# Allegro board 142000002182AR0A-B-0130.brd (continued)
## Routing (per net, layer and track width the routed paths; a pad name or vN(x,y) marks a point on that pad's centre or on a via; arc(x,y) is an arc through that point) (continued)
GND_1: length 19.4
  TOP w0.508: H1.5 21.23,24.93 C4.1 24.06,25.17 H1.4 ; 21.23,34.73 C3.1 ; 21.23,34.73 22.42,34.73 23.08,34.07 H1.2 ; 21.23,34.73 H1.1
GND_2: length 19.4
  TOP w0.508: H2.1 78.23,41.64 C23.1 76.37,44.16 H2.8 76.02,40.51 C22.1 73.34,39 H2.7
GND_3: length 20.5
  TOP w0.508: H4.4 206.08,34.07 C63.1 202.37,34.31 H4.6 198.77,37.14 C61.1 200.82,38.23 H4.7
GND_5: length 21.8
  TOP w0.508: H5.8 199.59,6.86 C62.1 199.5,3.14 H5.6 ; H5.2 208.84,6.86 C66.1 208.93,3.14 H5.4
GND_6: length 16.3
  TOP w0.381: 81.01,3.3 84.25,3.3 C24.1 83.32,5 H3.3 ; 75.44,3.68 C21.1 73.02,5 H3.7
GND_7: length 24.3
  TOP w0.508: H7.2 349.3,6.86 C114.1 349.4,3.14 H7.4 ; H7.6 338.69,3.14 C112.1 338.78,6.86 H7.8
GND_8: length 22.9
  TOP w0.508: H6.4 349.61,37.14 C115.1 349.59,40.86 H6.2 ; H6.7 341.7,38.86 341.67,38.89 337.41,38.89 C113.1 337.39,38.03 338.45,36.96 342.42,36.96 H6.6
GND_9: length 23.9
  TOP w0.508: H8.4 405.92,26.14 C141.1 406.82,29.86 H8.2 403.32,33.23 C138.1 399.61,33.77 H8.8
VCC_12P_FAN1_IN: length 3.8
  TOP w0.381: C9.2 31.44,40.97 31.5,41.02 ; C9.2 v3(32.31,40.26) ; C9.2 31.44,39.55 31.5,39.5
  TOP w0.508: 29.72,34.54 C6.1 29.03,33.84
  vias: v1(31.24,40.26) v3(31.04,42.16) v3(32.31,42.16) v3(32.31,41.27) v3(32.31,38.99)
VCC_12P_FAN1_OUT: length 4.7
  TOP w0.381: 39.12,33.53 39.06,33.58 C14.1 40.26,34.54
  TOP w0.508: C12.1 35.99,39.7 35.94,39.75 ; C12.1 36.7,40.64 ; C12.1 37.41,39.7 37.47,39.75
  vias: v1(36.32,41.66) v3(35.69,43.94) v3(36.83,43.94) v3(36.83,42.93) v3(38.03,43.94) v3(38.03,42.93)
VCC_12P_FAN2_IN: length 5.9
  TOP w0.508: C31.2 100.08,38.81 100.08,38.1 ; C31.2 99.9,40.19 99.82,40.26 ; C31.2 100.84,38.99 v3(101.22,39.37) ; 94.11,36.58 94.16,36.63 C28.1 95.25,35.69
  vias: v1(100.05,40.72) v3(99.94,42.16) v3(101.21,42.16) v3(101.21,41.27) v3(101.21,40.26)
VCC_12P_FAN2_OUT: length 3.3
  TOP w0.508: 106.55,35.43 106.37,35.61 C34.1 107.19,36.45 ; 105.1,42.36 C33.1 105.66,41.53
  vias: v1(104.9,42.29) v3(103.5,44.83) v3(104.13,43.56) v3(104.64,44.83) v3(105.79,44.07) v3(105.79,43.05)
VCC_12P_FAN3_IN: length 5.5
  TOP w0.508: C48.1 169.24,38.55 C50.2 ; 169.24,40.31 C50.2 ; C50.2 169.93,39.62 ; 167.77,33.4 167.71,33.45 C47.1 168.91,34.54
  vias: v1(169.42,40.01) v3(168.91,42.16) v3(168.91,41.27) v3(170.05,42.93) v3(170.05,41.78) v3(170.05,40.77)
VCC_12P_FAN3_OUT: length 4.8
  TOP w0.381: 174.17,39.7 C53.1 ; C53.1 174.88,40.39 ; C53.1 175.46,39.7
  TOP w0.508: 178.69,34.54 C55.1 177.24,33.58 177.55,33.27
  vias: v1(175.9,42.04) v3(173.16,43.43) v3(173.74,42.55) v3(174.3,43.43) v3(174.88,42.55) v3(175.51,43.43)
VCC_12P_FAN4_IN: length 4.1
  TOP w0.508: C87.2 237.44,39.7 ; C87.2 238.12,38.99 ; C87.2 237.44,38.41 237.49,38.35 ; 231.27,36.32 231.34,36.25 C84.1 232.28,35.43 232.41,35.31
  vias: v1(237.87,40.77) v3(237.74,42.16) v3(239.01,42.16) v3(239.01,41.27) v3(239.01,40.26) v3(239.01,38.99)
VCC_12P_FAN4_OUT: length 3.8
  TOP w0.508: 242.95,43.05 243.02,42.98 C89.1 243.71,42.42 ; C90.1 243.84,37.34 ; C90.1 243.02,37.54 243.46,37.97 ; C90.1 243.02,36.48
  vias: v1(242.82,42.16) v3(241.3,44.83) v3(241.94,43.56) v3(242.44,44.83) v3(244.6,43.43) v3(244.6,42.42)
VCC_12P_FAN5_IN: length 5
  TOP w0.381: C99.1 303.53,37.67 C98.2 304.04,38.23 304.17,38.35 ; 303.91,32.89 303.78,32.77 C97.1 302.84,32.06 302.89,32
  vias: v1(307.98,41.27) v3(305.82,38.86) v3(306.32,39.62) v3(306.7,38.86) v3(307.21,39.62) v3(307.72,38.86) v3(308.23,39.62)
VCC_12P_FAN5_OUT: length 5.1
  TOP w0.381: 312.8,35.81 312.8,36.9 C105.1 313.44,37.47 ; 313.06,32.38 312.93,32.26 C104.1 312.11,31.3 312.17,31.24
  vias: v1(311.79,44.2) v3(310.77,42.8) v3(310.77,41.91) v3(311.91,42.8) v3(311.91,41.91) v3(313.18,42.8) v3(313.18,41.78)
VCC_12P_FAN6_IN: length 5.4
  TOP w0.381: 372.75,38.99 C119.2 372.24,38.3 C120.1
  TOP w0.508: 372.36,33.91 C118.1 371.17,33.33 371.6,32.89
  vias: v1(376.3,44.83) v3(374.06,38.9) v3(374.2,39.83) v3(374.79,39.26) v3(374.87,40.29) v3(375.6,39.32) v3(375.67,40.13)
VCC_12P_FAN6_OUT: length 6
  TOP w0.381: 380.49,42.16 380.69,41.96 C126.1 381.76,41.27 ; 382.27,35.18 382.09,35.36 C130.1 ; C129.1 382.09,37.65 C130.1 ; C130.1 383.41,36.2
  vias: v1(379.48,45.34) v3(380.87,43.05) v3(381.38,42.29) v3(381.76,43.05) v3(382.19,42.29) v3(382.65,43.05) v3(383,42.16)
VCC_CL_FAN1F: length 1
  BOTTOM w0.381: v3(39.24,28.83) v1(38.23,28.83)
VCC_CL_FAN1R: length 1.5
  BOTTOM w0.381: v1(31.42,27.41) 30.38,28.45 v3(30.35,28.45)
VCC_CL_FAN2F: length 0.9
  BOTTOM w0.381: v3(106.43,31.5) v1(105.51,31.5)
VCC_CL_FAN2R: length 0.9
  BOTTOM w0.381: v3(88.9,36.83) v1(88.9,35.92)
VCC_CL_FAN3F: length 1.2
  BOTTOM w0.381: v3(177.42,28.19) v1(176.59,29.02)
VCC_CL_FAN3R: length 1.1
  BOTTOM w0.381: v3(167.77,28.45) v1(167.77,29.59)
VCC_CL_FAN4F: length 1
  BOTTOM w0.381: v3(243.46,32.26) v1(243.46,31.24)
VCC_CL_FAN4R: length 1
  BOTTOM w0.381: v3(226.19,35.69) v1(226.19,36.7)
VCC_CL_FAN5F: length 1.3
  BOTTOM w0.254: v1(310.9,25.53) 312.04,25.53 v3(312.17,25.65)
VCC_CL_FAN5R: length 1.1
  BOTTOM w0.254: v1(302.77,26.29) v3(303.91,26.29)
VCC_CL_FAN6F: length 1.2
  BOTTOM w0.254: v3(381.89,29.97) 381.51,30.35 v1(381.51,30.99)
VCC_CL_FAN6R: length 1
  BOTTOM w0.254: v1(371.35,28.83) v3(372.36,28.83)
VCCA_FAN_CPLD: length 64.2
  TOP w0.254: U7.D3 v2(133.48,21.34) ; U7.D4 v2(133.48,20.54) ; U7.D10 133.47,15.75 v2(133.48,15.75) ; U7.K4 v2(127.88,21.34) ; U7.K9 v2(128.68,17.34)
  TOP w0.381: v3(137.42,7.24) 137.03,6.86 L9.2 137.03,5.21 v3(136.53,4.7) ; v3(144.29,12.73) 144.71,13.14 145.74,13.14 146.94,14.35 146.94,21.95 v3(147.32,22.33)
  BOTTOM w0.33: 132.47,16.77 133.48,15.76 v2(133.48,15.75)
  BOTTOM w0.381: v2(133.48,15.75) 133.48,15.61 133.93,15.16 C159.1 133.93,13.05 134.87,12.11 134.87,6.61 136.53,4.95 v3(136.53,4.7) ; 132.47,16.77 130.05,16.77 129.54,17.28 C151.1 128.7,17.33 v2(128.68,17.34) 128.68,18.95 127.82,19.82 C147.1 127.82,21.27 v2(127.88,21.34) ; v2(133.48,20.54) v2(133.48,21.34) 133.6,21.46 134.82,21.46 C161.1 135.41,21.23 137.77,21.23 137.93,21.07 138.65,21.07 139.46,21.88 139.95,21.88 140.48,22.42 146.37,22.42 146.46,22.33 v3(147.32,22.33) ; v3(137.42,7.24) 137.42,7.27 140.31,10.16 v1(140.31,10.31) 141.13,11.13 141.61,11.13 142.54,12.06 143.38,12.06 144.04,12.73 v3(144.29,12.73)
VDD3P3: length 1337.3
  TOP w0.254: v2(131.08,19.74) U7.G6 v2(130.28,18.94) U7.H7 U7.G8 ; v2(128.68,21.34) 129.08,21.74 U7.J3 v2(128.68,22.14) U7.K3 ; U7.G8 U7.F7 v2(131.88,18.94) ; U7.G8 v2(131.08,17.34) ; U7.J11 v2(129.48,14.94) ; U7.G11 v2(131.08,15.74) U7.F11 ; U7.F11 v2(131.88,14.94) ; U7.F11 v2(131.88,15.74) ; v2(131.88,22.94) U7.F2 v2(131.08,22.14) U7.G3 ; v2(127.88,17.34) 127.88,17.47 127.61,17.74 U7.L8 v2(127.88,18.14) U7.L7 v2(127.88,18.94) U7.L6 ; U7.H11 v2(129.48,15.74)
  TOP w0.381: C45.2 163.4,22.66 165.24,20.81 CONN3.4 ; LED6.A1 419.14,47 420.45,48.31 C142.1 420.41,48.4 LED6.A2 ; 355.6,35.1 355.6,22.61 v3(354.71,21.72) ; 355.6,35.1 360.72,40.22 372.77,40.22 373.89,41.34 R150.1 ; 355.6,35.1 353.28,37.42 353.28,40.18 352.43,41.03 C116.1 ; R16.2 44.5,5.92 v3(44.58,5.84) ; R62.2 126.49,27.84 v3(126.85,27.48) ; R19.2 v3(58.42,5.84) R23.2 ; v3(93.34,27.69) 94.49,28.83 R31.1 ; 145.16,4.95 145.09,5.03 R88.2 144.76,6.17 v3(144.28,6.17) 143.79,6.17 R80.2 143.46,5.51 144.02,4.95 ; R73.2 R74.2 R75.2 R76.2 v3(144.27,21.56) R82.2 ; R3.2 v3(13.72,12.45) ; v3(170.69,22.23) 174.22,25.76 174.22,32.99 R106.1 ; C116.1 352.29,47.82 352.02,47.82 351.43,48.4 LED5.A2 ; C116.1 352.15,47.68 351.47,47 LED5.A1 ; v3(115.06,25.02) 115.86,25.02 117.76,23.11 R54.2 R55.2 ; U7.C7 v2(133.48,18.94) U7.C6 ; LED4.A2 LED4.A1 280.34,46.7 C96.1 276.35,45.59 260.73,29.97 v3(260.73,21.84) ; R129.1 249.68,36.58 250.19,36.07 250.19,33.78 250.5,33.47 Q10.5 252.15,32.62 C95.1 252.15,30.83 250.85,29.53 247.42,29.53 245.45,27.56 233.68,27.56 231.52,29.72 R124.1 ; 11.18,40.25 28.93,40.25 29.27,40.59 29.27,42.78 R7.1 ; R4.2 13.74,11.05 v3(13.72,11.07) ; R5.2 R6.2 v3(16.76,18.67) ; R2.2 v3(14.1,13.84) ; U8.16 153.25,19.27 152.58,18.59 C44.1 C43.1 v3(150.11,18.59) ; R138.1 309.32,30.79 310.39,29.72 v3(310.39,19.3) ; R1.2 v3(14.1,15.11) ; v3(299.72,21.21) 298.96,21.97 298.96,39.05 299.34,39.43 305.12,39.43 305.56,39.88 R136.1 ; U7.C8 v2(134.28,17.34)
  TOP w0.508: v3(149.96,9.64) R90.2 149.13,10.44 149.1,10.41 ; v3(113.92,13.72) R40.1 R41.1 ; LED2.A1 LED2.A2 144.11,48.6 C42.1 144.83,46.05 150.66,40.22 162.05,40.22 ; R83.2 R84.2 R85.2 R86.2 R87.2 v3(146,14.43) ; v3(137.12,8) 136.27,8 135.51,7.24 L9.1 135.51,4.97 v3(135.19,4.65) ; 213.67,39.88 213.79,40.01 235.44,40.01 235.9,40.47 235.9,42.27 237.11,43.48 R125.1 ; 213.67,39.88 213.67,36.53 203.27,26.14 193.14,26.14 v3(188.47,21.46) ; 213.67,39.88 C69.1 212.95,48.6 LED3.A2 LED3.A1 ; Q1.5 17.62,32.23 18.16,32.77 C2.1 17.6,34.22 17.37,34.44 17.37,35.59 v3(17.27,35.69) 16.89,36.07 C1.1 15.95,36.88 15.3,37.53 Q2.5 ; R92.2 151.89,14.23 151.13,13.47 v3(149.87,13.47) 149.87,18.35 v3(150.11,18.59) ; C71.1 214.2,17.1 ; C71.1 C72.1 ; C71.1 214.78,16.28 ; R157.2 378.84,2.64 378.21,2.01 376.13,2.01 369.95,8.18 369.95,19.5 v3(373.79,23.34) 374.58,24.13 374.62,24.13 379.22,28.73 379.22,32.26 378.03,33.45 R156.1 ; C73.1 218.14,17.1 C74.1 ; C73.1 C72.1 ; C73.1 216.81,16.28 ; v3(89.79,26.92) 89.53,26.92 83.05,33.41 83,33.41 ; Q6.5 117.4,32.62 C39.1 ; C142.1 420.5,46.48 v3(419.99,45.97) ; R112.1 184.95,33.78 Q8.5 186.11,32.62 C60.1 185.17,31.06 185.17,27.8 180.15,22.78 v3(180.15,22.75) ; R42.1 R43.1 115.24,17.27 v3(114.43,17.27) ; 83,33.41 82.61,33.02 75.23,33.02 69.09,39.16 69.09,42.29 70.94,44.14 C20.1 73.53,45.47 74.14,46.07 LED1.A1 LED1.A2 ; 83,33.41 83,39 83,39.52 83.69,40.22 97.81,40.22 98.31,40.73 98.31,42.87 R32.1 ; R161.1 389.89,32.71 C133.1 390.22,32.64 391.58,32.64 Q14.5 391.82,32.39 391.82,31.26 v3(391.81,31.24) ; 162.05,40.22 162.05,32.09 157.03,27.08 v3(157,27.08) 156.77,27.3 149.22,27.3 144.73,31.8 C41.1 138.01,31.8 137.64,32.17 137.64,32.54 137.16,33.02 L10.2 135.46,33.02 R66.1 ; 162.05,40.22 166.71,40.22 167.26,40.77 167.26,42.92 R103.1 ; C111.1 v3(321.49,21.59) ; C111.1 320.94,28.32 317.77,31.5 R142.1 ; C111.1 321.49,29.44 Q12.5 ; R94.2 153.01,9.55 153.03,9.53 ; C72.1 215.8,16.36 ; v3(125.09,27.05) 124.84,27.3 R61.2 ; v3(117.09,28.19) 117.09,30.4 117.4,30.71 C39.1 ; C39.1 114.68,31.88 113.23,33.33 R37.1 ; R95.2 154.03,9.63 153.92,9.53 ; v3(37.34,23.01) 36.55,23.01 35.89,23.68 35.89,32.47 34.74,33.61 R9.1 ; v3(158.5,26.29) 161.09,26.29 163.4,23.98 C45.2 164.08,23.62 165.48,22.23 v3(170.69,22.23) ; v3(127,5.59) 125.09,7.49 R59.2 R58.2 R57.2 R56.2 ; R102.2 v3(170.69,11.05) R104.2 ; v3(7.87,37.21) 7.87,38.23 9.9,40.25 11.18,40.25 ; v3(45.65,26.6) 48.31,29.26 C19.1 48.31,34.27 Q4.5 46.9,34.99 45.69,33.78 R15.1
  TOP w0.635: 223.77,16 225.04,16 v3(231.52,22.48) 233.68,24.64 233.68,27.56
  TOP w0.762: v3(184.78,20.83) 175.01,11.05 v3(174.62,11.05) 172.85,9.27 165.99,9.27 165.02,8.31 154.25,8.31 153.8,8.76 ; v3(134.04,5.59) 134.04,6.09
  TOP w1.016: 211.71,15.37 206.38,15.37 203.58,18.16 203.58,20.45 v3(203.45,20.57)
  V3 w0.381: v3(135.19,4.65) 136.26,3.58 145.57,3.58 v3(146.3,4.32)
  BOTTOM w0.381: v3(14.1,15.11) v3(14.1,13.84) 13.72,13.46 v3(13.72,12.45) v3(13.72,11.07) ; C154.1 130.68,14.73 ; C154.1 131.14,14.17 ; C154.1 130.23,14.17 ; 127.13,18.29 C146.1 127.54,18.14 v2(127.88,18.14) ; C155.1 130.84,23.14 ; C155.1 C152.1 ; C155.1 C158.1 ; C158.1 132.59,23.75 132.59,23.75 ; C158.1 131.85,22.97 v2(131.88,22.94) ; 127.79,22.38 127.45,22.71 C145.1 ; C153.1 131.04,22.1 v2(131.08,22.14) ; C153.1 130.38,22.66 ; C153.1 130.38,21.39 130.43,21.34 ; C144.1 128.14,23.88 ; C144.1 C145.1 ; C144.1 127.45,24.71 127.51,24.77 ; v2(131.08,17.34) 131.39,17.65 C156.1 131.88,18.53 v2(131.88,18.94) ; C152.1 129.82,23.14 ; C152.1 C149.1 128.8,23.14 128.65,22.99 ; 125.48,18.03 125.53,18.09 C143.1 126.11,17.27 ; C150.1 130.46,19.61 ; C150.1 129.99,20.27 130.3,20.57 ; C150.1 130.28,19.32 v2(130.28,18.94) ; C145.1 128.02,22.86 ; 128.78,15.49 C148.1 129.47,14.93 v2(129.48,14.94) ; v3(135.19,4.65) 136.25,3.58 145.57,3.58 v3(146.3,4.32)
  BOTTOM w0.508: v3(144.27,21.56) 144.4,21.44 147.09,21.44 149.94,18.59 v3(150.11,18.59) ; v3(231.52,22.48) 232.16,21.84 v3(260.73,21.84) 299.08,21.84 v3(299.72,21.21) 301.62,19.3 v3(310.39,19.3) 318.01,19.3 320.29,21.59 v3(321.49,21.59) 321.62,21.72 v3(354.71,21.72) 372.17,21.72 v3(373.79,23.34) 374.45,23.99 379.89,23.99 384.98,29.08 389.73,29.08 391.81,31.15 v3(391.81,31.24) 391.89,31.24 394.91,34.26 397.06,34.26 400.04,37.24 411.25,37.24 v3(419.99,45.97) ; 133.35,19.68 133.4,19.74 C160.1 C162.1 ; v3(146,14.43) 146.23,14.19 147.83,14.19 148.42,13.6 149.74,13.6 v3(149.87,13.47) 151,12.34 151,10.68 v3(149.96,9.64) ; v3(157,27.08) 157.78,26.29 v3(158.5,26.29) ; 118.11,14.86 R170.1 119.69,15.82 119.63,15.88 ; v3(170.69,11.05) v3(174.62,11.05) ; v3(16.76,18.67) 22.07,13.36 22.07,11.07 ; v3(137.12,8) 137.12,8.04 137.1,8.06 137.1,13.02 C164.1 138.1,14.02 C163.1 136.78,15.37 135.78,16.36 135.78,17.58 135.38,17.99 134.75,17.99 134.28,17.52 v2(134.28,17.34)
  BOTTOM w0.635: 133.6,11.56 133.48,11.68 C157.1 132.59,13.21 132.72,13.34
  BOTTOM w0.762: v3(128.78,4.83) 128.02,5.59 v3(127,5.59) 126.24,5.59 124.69,4.04 88.99,4.04 81.85,11.18 72.9,11.18 67.56,5.84 v3(58.42,5.84) v3(44.58,5.84) 43.69,6.73 26.42,6.73 22.07,11.07 v3(13.72,11.07) 12.93,10.29 10.54,10.29 4.06,16.76 4.06,34.67 v1(4.32,34.92) 6.6,37.21 v3(7.87,37.21) 14.48,37.21 16,35.69 v3(17.27,35.69) 17.27,36.58 18.54,37.85 22.73,37.85 24.51,36.07 24.51,31.88 25.65,30.73 25.65,25.23 24.23,23.81 24.23,22.73 25,21.97 36.3,21.97 v3(37.34,23.01) 37.74,22.61 41.66,22.61 v3(45.65,26.6) 45.88,26.37 v1(55.88,26.37) 89.24,26.37 v3(89.79,26.92) 92.58,26.92 v3(93.34,27.69) 100.08,20.95 v3(109.73,20.95) ; v3(144.28,6.17) 144.28,6.3 147.83,9.85 v3(147.83,10.67) ; v3(135.19,4.65) 134.25,5.59 v3(134.04,5.59) 134.04,11.12 133.6,11.56
  vias: v3(110.49,20.32) v3(114.05,18.16) v3(122.68,28.45) v3(125.73,26.54) v3(202.31,20.57)
VDD3P3_BODE: length 4.2
  TOP w0.381: v3(225.76,19.33) R122.2 ; R122.2 C79.1 ; R122.2 224.94,18.26 R121.1
  BOTTOM w0.381: v1(224.82,19.33) v3(225.76,19.33)
VDD3P3_EN: length 4.7
  TOP w0.381: R119.1 C80.1 223.55,23.6 v3(223.16,23.98) U12.7
  BOTTOM w0.381: v1(221.97,23.98) v3(223.16,23.98)
25MHZ_OUT: length 4.3
  TOP w0.254: OSC1.3 129.92,30.62 129.92,29.58 v3(129.95,29.56) 129.92,29.53 R63.2
  BOTTOM w0.254: v3(129.95,29.56) 129.76,29.75 128.68,29.75 v1(128.11,30.32)
25MHZ_OUT_R: length 10.4
  TOP w0.127: 129.49,23.88 129.49,22.3 129.62,22.17 130.04,22.17 130.28,21.93 130.28,19.74 U7.H6
  TOP w0.254: 129.49,23.88 129.49,24.92 129.84,25.27 v3(129.84,26.42) 129.84,27.66 R63.1
  BOTTOM w0.254: v1(128.83,26.52) 128.93,26.42 v3(129.84,26.42)
BOARD_ID_0: length 6.4
  TOP w0.254: v2(126.29,14.94) 126.29,14.95 U7.M11
  BOTTOM w0.254: R170.2 121.59,14.86 R171.1 124.15,14.93 v1(124.33,15.11) 124.52,14.93 126.28,14.93 v2(126.29,14.94)
BOARD_ID_1: length 11.4
  TOP w0.254: U7.N7 125.35,18.54 124.57,17.77 122.9,17.77 122.2,17.07 v3(121.54,17.07) ; R50.1 117.47,18.16 v3(117.35,18.03) 117.22,18.16 R42.2
  BOTTOM w0.254: v3(121.54,17.07) 121.11,17.5 119.41,17.5 119.13,17.78 v1(118.75,17.78) 117.6,17.78 v3(117.35,18.03)
BS_VDD3P3: length 1
  BOTTOM w0.254: v1(217.32,26.54) 216.81,26.04 v3(216.53,26.04)
CPLD_CONFIG_DONE: length 14.6
  TOP w0.127: 136.15,20.55 136.13,20.57 134.31,20.57 U7.C5
  TOP w0.254: 136.15,20.55 136.76,20.55 137.29,21.08 139.06,21.08 139.55,21.57 v3(140.66,21.57) 140.77,21.57 141.48,20.85 145.72,20.85 146,21.13 R82.1
  BOTTOM w0.254: v1(139.87,21.06) 140.06,21.06 140.57,21.57 v3(140.66,21.57)
CPLD_CONFIG_SEL: length 14.6
  TOP w0.254: v3(139.06,17.93) 139.24,17.75 141.28,17.75 141.46,17.93 143.15,17.93 143.46,18.23 R78.1 R84.1 ; U7.D7 v2(132.68,18.94)
  BOTTOM w0.254: v2(132.68,18.94) 133.19,18.43 133.75,18.43 134.32,19 137.37,19 v1(138.15,18.22) 138.52,18.22 138.81,17.93 v3(139.06,17.93)
CPLD_CRC: length 14.7
  TOP w0.127: U7.D6 133.51,19.77 135.88,19.77
  TOP w0.254: 135.88,19.77 136.58,19.08 137.41,19.08 138.68,20.35 143.21,20.35 143.46,20.09 R77.1 143.89,19.68 v3(144.27,20.07) R83.1
  BOTTOM w0.254: v1(145.29,20.04) 145.26,20.07 v3(144.27,20.07)
CPLD_DEV_CLRN: length 12.9
  TOP w0.127: U7.B9 135.11,16.51 136.08,16.51 136.46,16.13 136.91,16.13 137.52,16.74
  TOP w0.254: R87.1 144.5,15.24 v3(144.23,15.51) 144.22,15.49 143.58,15.49 R71.1 143.33,15.55 142.77,16.1 141.24,16.1 140.61,16.74 137.52,16.74
  BOTTOM w0.254: v3(144.23,15.51) v1(145.16,15.51)
CPLD_DEV_OE: length 14.1
  TOP w0.127: U7.D8 133.45,18.11 135.71,18.11 136.17,17.65
  TOP w0.254: 136.17,17.65 137.42,17.65 137.83,17.25 140.84,17.25 141.47,16.61 143.05,16.61 143.46,17.02 R79.1 v3(144.27,17.27) R85.1
  BOTTOM w0.254: v3(144.27,17.27) 143.43,17.27 v1(143.36,17.2)
CPLD_NCONFIG: length 14.3
  TOP w0.254: U7.E7 v2(132.68,18.14) ; R86.1 144.48,16.26 144.37,16.36 v3(144.22,16.36)
  BOTTOM w0.254: v3(144.22,16.36) 143.03,16.36 142.77,16.61 141.46,16.61 140.54,17.53 v1(140.21,17.53) 139.95,17.27 138.02,17.27 136.8,18.49 134.54,18.49 134.09,18.05 132.77,18.05 v2(132.68,18.14)
CPLD_NSTATUS: length 11
  TOP w0.127: 135.8,21.37 134.31,21.37 U7.C4
  TOP w0.254: R76.1 141.71,21.56 v3(141.58,21.69) 141.5,21.69 140.74,22.45 137.58,22.45 136.52,21.4 135.83,21.4 135.8,21.37
  BOTTOM w0.254: v1(142.75,21.59) 142.62,21.46 141.81,21.46 v3(141.58,21.69)
CPLD_TCK: length 52.9
  TOP w0.127: U7.G2 131.05,22.91 131.05,23.49 131.33,23.77
  TOP w0.254: 131.33,23.77 131.74,23.77 133.43,25.46 133.73,25.46 135.07,26.81 R65.2 135.07,27.9 136.76,29.59 143.63,29.59 148.49,24.74 157.48,24.74 160.57,21.64 160.57,18.97 v3(160.27,18.67) ; R99.2 159.08,11.05 R101.2 162.23,11.99 162.7,12.46 CONN3.1 162.7,15.48 162.05,16.13 v3(161.16,16.13)
  BOTTOM w0.254: v3(161.16,16.13) 160.27,17.02 v1(160.27,17.4) v3(160.27,18.67)
CPLD_TCK_A: length 7.6
  TOP w0.254: R65.1 133.82,27.47 133.82,27.38 133.74,27.29 133.74,26.54 v3(133.73,26.54) ; U7.H1 129.88,24.3 131.32,25.74 v3(131.32,26.04)
  BOTTOM w0.254: v3(131.32,26.04) v1(132.08,26.8) 132.34,26.53 133.73,26.53 v3(133.73,26.54)
CPLD_TDI: length 75.3
  TOP w0.254: R97.2 156.06,10.37 156.9,9.53 163.42,9.53 164.29,10.39 172.67,10.39 172.92,10.64 R104.1 172.86,11.11 CONN3.9 172.86,16.37 171.99,17.24 166.78,17.24 v3(166.5,17.53) ; v3(159.56,20.83) 159.56,21.22 157.06,23.72 148.06,23.72 143.31,28.47 137.55,28.47 136.98,27.9 R67.2 136.98,27.15 135.45,25.63 v3(135.25,25.63) ; v2(131.09,20.54) 131.09,20.53 U7.F5
  BOTTOM w0.254: v2(131.09,20.54) 131.09,20.63 135.25,24.8 v3(135.25,25.63) ; v3(166.5,17.53) 165.29,18.73 v1(164.85,18.73) 163.77,18.73 162.31,20.19 160.19,20.19 v3(159.56,20.83)
CPLD_TDI_A: length 7.4
  TOP w0.254: R67.1 136.07,27.18 v3(135.89,27) 135.89,26.86 135.64,26.6 135.37,26.6 132.28,23.51 U7.E1
  BOTTOM w0.254: v1(134.93,26.48) 135.17,26.72 135.62,26.72 v3(135.89,27)
CPLD_TDO: length 52.8
  TOP w0.127: U7.F6 131.88,19.74 v2(131.88,20.54)
  TOP w0.254: v3(158.75,20.7) 158.75,21.31 156.84,23.22 147.85,23.22 143.26,27.81 R70.2 138.88,26.49 138.18,25.78 v3(138.18,25.27) ; R100.2 159.36,16.1 160.4,17.14 v3(164.08,17.14) 164.41,17.14 165.24,16.32 CONN3.3
  BOTTOM w0.254: v3(158.75,20.7) 159.77,19.68 161.74,19.68 v1(162.62,18.8) 164.08,17.34 v3(164.08,17.14) ; v3(138.18,25.27) 138.18,25.11 137.18,24.11 135.45,24.11 v2(131.88,20.54)
CPLD_TDO_A: length 8.3
  TOP w0.254: R70.1 137.98,27.22 v3(136.79,26.03) 136.58,26.03 135.67,25.12 134.39,25.12 133.08,23.81 U7.D1
  BOTTOM w0.254: v1(136.99,26.92) 136.99,26.23 v3(136.79,26.03)
CPLD_TMS: length 66.2
  TOP w0.254: v3(161.54,18.41) 161.59,18.46 161.59,22.06 157.9,25.76 149,25.76 144.15,30.61 136.34,30.61 134.05,28.32 133.59,28.32 133.17,27.9 R64.2 133.17,27.51 133.1,27.43 133.1,26.83 133.08,26.81 133.08,26.06 132.72,25.7 132.72,25.66 130.68,23.63 U7.G1 ; v3(166.5,16.51) 167.26,16.51 167.78,15.99 CONN3.5 167.69,14.66 R102.1 164.23,11.05 163.21,10.03 157.41,10.03 157.07,10.37 R98.2
  BOTTOM w0.254: v3(166.5,16.51) 166.37,16.38 v1(165.23,16.38) 163.07,16.38 161.54,17.91 v3(161.54,18.41)
CPLD_TMS_A: length 9.8
  TOP w0.127: 130.31,23.58 130.31,22.97 U7.H2
  TOP w0.254: v3(132.85,29.56) 132.85,29.09 132.26,28.5 R64.1 132.26,25.96 130.31,24.01 130.31,23.58
  BOTTOM w0.254: v1(134.24,29.97) 134.11,29.84 133.14,29.84 v3(132.85,29.56)
CPU_FAN_CPLD_RST_N: length 90.5
  TOP w0.254: U7.D13 133.16,13.67 133.16,13.26 133.1,13.2 133.1,12.83 134.14,11.79 134.14,11.43 133.88,11.18 133.88,10.39 134.06,10.21 134.06,8.29 132.16,6.38 129.4,6.38 127.95,4.93 126.73,4.93 124.82,6.83 107.54,6.83 105.48,8.89 84.11,8.89 79.28,13.72 v3(72.26,13.72) 70.23,13.72 67.69,11.18 67.69,7.87 65.66,5.84 R27.2 65.1,6.8 65.49,7.19 CONN2.17
  BOTTOM w0.254: v3(72.26,13.72) v1(72.26,14.73)
CPU_UPGRADE_CPLD_TCK: length 6.4
  TOP w0.254: R99.1 158.04,11.62 v3(157.48,12.19) 157.48,12.7 156.57,13.61 U8.6
  BOTTOM w0.254: v3(157.48,12.19) 157.86,11.8 157.86,11.43 158.37,10.93 v1(158.37,10.41)
CPU_UPGRADE_CPLD_TDI: length 5
  TOP w0.254: R97.1 156.06,11.53 v3(155.42,12.17) 155.42,13.43 155.27,13.58 U8.4
  BOTTOM w0.254: v1(156.09,13.08) 155.42,12.41 v3(155.42,12.17)
CPU_UPGRADE_CPLD_TDO: length 6.2
  TOP w0.254: R100.1 159.36,12.52 v3(158.91,12.07) 157.22,13.76 U8.7
  BOTTOM w0.254: v3(158.91,12.07) 159.42,11.56 v1(160.15,11.56)
CPU_UPGRADE_CPLD_TMS: length 5.2
  TOP w0.254: R98.1 157.07,11.66 156.56,12.17 v3(156.44,12.17) 156.44,13.02 155.92,13.54 U8.5
  BOTTOM w0.254: v1(156.46,10.97) 156.44,11 v3(156.44,12.17)
CPU_UPGRADE_I2C_INT_L: length 25.8
  TOP w0.254: v3(151.1,14.83) 151.12,14.83 151.6,15.31 R92.1 151.89,15.49 155.27,18.87 U8.13 ; U7.A7 135.69,18.54 136.23,18.01 138.42,18.01 138.96,18.54 139.32,18.54 139.45,18.41 v3(140.96,18.41)
  BOTTOM w0.254: v3(140.96,18.41) 140.96,18.41 140.96,18.3 141.3,17.96 146.71,17.96 v1(147.15,17.51) 147.15,16.81 149.14,14.81 151.08,14.81 v3(151.1,14.83)
EN_FAN1: length 125.1
  TOP w0.254: U3.7 41.52,33.23 42.08,33.78 v3(42.42,33.78) R15.2 ; U1.7 31.49,33.23 32.04,33.78 v3(32.38,33.78) R9.2 33.84,33.36 34.09,33.11 34.35,33.11 35.25,32.2 35.25,23.41 36.31,22.35 42.34,22.35 47.54,27.56 82.94,27.56 88.29,22.2 113.61,22.2 116.4,19.41 120.89,19.41 121.54,18.75 123.9,18.75 124.45,19.3 125.84,19.3 U7.N6
  BOTTOM w0.254: v3(32.38,33.78) 32.89,33.28 39.63,33.28 v1(40.13,33.78) v3(42.42,33.78)
EN_FAN2: length 47.9
  TOP w0.127: 126.6,23.96 127.07,23.49 127.07,22.95 U7.L2
  TOP w0.254: U4.7 93.93,34.17 94.49,33.61 v3(94.49,32.77) R31.2 ; 112.32,34.81 112.32,34.98 112.8,35.46 114.78,35.46 116.2,34.04 117.47,34.04 117.98,33.53 117.98,32.89 118.34,32.54 119.53,32.54 120.71,31.36 120.71,27.97 122.75,25.93 124.62,25.93 126.6,23.96 ; 112.32,34.81 112.05,34.81 111.17,35.69 v3(109.73,35.69) 109.39,35.69 108.83,35.13 U6.7 ; 112.32,34.81 R37.2
  BOTTOM w0.254: v3(109.73,35.69) v1(106.65,35.69) 104.9,35.69 101.98,32.77 v3(94.49,32.77)
EN_FAN3: length 86.4
  TOP w0.254: v3(138.4,21.84) 137.47,21.84 136.65,21.02 135.56,21.02 U7.A4 ; U9.7 170.17,33.23 170.73,33.78 v3(171.07,33.78) R106.2 ; v3(174.12,13.06) 174.37,13.31 174.37,17.91 184.24,27.78 184.24,32.06 183.18,33.12 182.53,33.12 182.04,33.6 R112.2 v3(180.59,33.78) 180.25,33.78 179.7,33.23 U11.7
  BOTTOM w0.254: v3(138.4,21.84) 139.01,22.45 139.59,22.45 140.13,22.99 151.09,22.99 153.16,20.91 153.16,19.73 159.69,13.21 173.96,13.21 v3(174.12,13.06) ; v3(171.07,33.78) v1(179.34,33.78) v3(180.59,33.78)
EN_FAN4: length 135.9
  TOP w0.127: U7.B12 134.96,14.54 135.39,14.11 135.71,14.11 136.88,12.93 136.97,12.93
  TOP w0.254: R129.2 v3(246.76,36.58) 246.42,36.58 245.86,36.02 U15.7 ; U13.7 230.96,33.79 231.52,33.23 v3(231.52,32.89) R124.2 231.21,31.44 230.85,31.08 230.85,30.93 229.38,29.46 221.23,29.46 219.07,31.62 210.41,31.62 203.78,24.99 193.65,24.99 188.85,20.19 187.38,20.19 173.21,6.02 148.95,6.02 146.1,8.86 142.27,8.86 138.54,12.59 138.01,12.59 137.67,12.93 136.97,12.93
  BOTTOM w0.254: v3(231.52,32.89) 238.12,32.89 241.81,36.58 v1(245.57,36.58) v3(246.76,36.58)
EN_FAN5: length 242.8
  TOP w0.254: R138.2 308.28,31.5 v3(307.59,31.5) 306.32,31.5 306.06,31.23 U16.7 ; v3(320.68,10.19) 320.68,27.69 317.76,30.61 v3(317.54,30.61) 317.12,30.61 316.54,31.19 R142.2 315.47,31.5 315.09,31.11 314.2,31.11 314.06,30.98 U18.7 ; v3(133.13,8.29) 133.13,8.37 133.28,8.52 133.28,9.21 132.47,10.02 132.47,12.18 132.24,12.4 132.24,13.7 U7.E13
  BOTTOM w0.254: v3(307.59,31.5) 316.65,31.5 v3(317.54,30.61) ; v3(133.13,8.29) 133.28,8.14 133.28,5.27 135.54,3.01 146.27,3.01 146.94,3.68 v1(147.19,3.68) 148.84,5.33 175.59,5.33 180.44,10.18 243.35,10.18 245.87,12.7 293.83,12.7 296.2,10.34 320.52,10.34 v3(320.68,10.19)
EN_FAN6: length 297.2
  TOP w0.254: v3(370.84,11.43) 370.84,19.45 379.86,28.47 379.86,32.52 378.84,33.54 378.84,34.42 378.54,34.72 v3(377.12,34.72) R156.2 374.78,33.91 374.64,33.77 U19.7 ; U7.B10 134.63,16.14 134.29,15.8 134.29,15.74 v2(134.28,15.73) ; U22.7 384.29,34.53 384.81,35.05 v3(385.83,35.05) R161.2
  BOTTOM w0.254: v3(385.83,35.05) 385.42,34.65 377.19,34.65 v3(377.12,34.72) ; v3(370.84,11.43) 370.59,11.68 330.33,11.68 328.98,10.34 325.36,10.34 324.85,10.85 296.41,10.85 294.05,13.21 245.65,13.21 243.14,10.69 180.23,10.69 175.38,5.84 146.94,5.84 v1(146.69,5.59) 146.21,5.59 144.78,4.15 138.13,4.15 135.45,6.84 135.45,12.34 135.23,12.56 134.5,13.28 134.5,15.51 v2(134.28,15.73)
EN_FAN7: length 157.7
  TOP w0.127: 132.67,13.31 132.67,14.15 U7.E12
  TOP w0.254: v3(133.13,10.34) 133.21,10.42 133.21,10.43 133.22,10.44 133.22,12.06 132.67,12.61 132.67,13.31 ; v3(27.18,7.98) v3(9.27,7.98) 4.57,12.67 4.57,19.9 4.95,20.28 CONN1.25
  BOTTOM w0.254: v3(133.13,10.34) 133.06,10.4 132.7,10.4 131.96,9.66 131.96,8.82 130.63,7.49 126.24,7.49 124.06,5.31 90.24,5.31 77.89,17.65 53.25,17.65 50.2,14.61 33.81,14.61 v3(27.18,7.98) ; v3(9.27,7.98) v1(9.27,8.89)
EN_FAN8: length 140.4
  TOP w0.254: CONN1.28 12.09,19.01 12.83,18.28 12.83,12.4 13.49,11.73 25.45,11.73 v3(26.92,13.21) ; v3(131.3,9.9) 131.3,11.16 131.53,11.39 131.53,13.69 U7.F13
  BOTTOM w0.254: v3(26.92,13.21) v1(28.91,15.19) 29.34,15.62 49.06,15.62 52.62,19.18 78.52,19.18 91.38,6.32 123.64,6.32 125.82,8.51 129.78,8.51 131.18,9.9 v3(131.3,9.9)
FAN1_IN_PWM: length 8.4
  TOP w0.254: R10.1 v3(39.83,45.09)
  BOTTOM w0.254: v1(39.14,45.81) 39.83,45.12 v3(39.83,45.09) 40.13,45.39 40.13,47.12 39.14,48.11 U2.4
FAN1_LED_G: length 75.1
  TOP w0.127: U7.M2 126.25,22.97 125.59,22.97
  TOP w0.254: R29.1 v3(67.36,42.93) 67.36,39.99 75.22,32.13 83.39,32.13 89.26,26.26 111.34,26.26 111.87,26.8 120.45,26.8 122.68,24.56 123.64,23.6 124.94,23.6 125.57,22.97 125.59,22.97
  BOTTOM w0.254: v3(67.36,42.93) v1(68.33,42.93)
FAN1_LED_G1: length 3.4
  TOP w0.254: LED1.C1 v3(69.22,47.2) 68.36,47.2 R29.2
  BOTTOM w0.254: v3(69.22,47.2) v1(68.2,47.2)
FAN1_LED_R: length 77.5
  TOP w0.254: U7.N2 125.5,22.54 124.94,23.1 123.43,23.1 120.24,26.29 112.08,26.29 111.55,25.76 89.05,25.76 83.18,31.62 75.01,31.62 66.29,40.34 v3(66.29,45.85) 66.29,48.26 66.55,48.51 R28.1
  BOTTOM w0.254: v3(66.29,45.85) v1(65.28,45.85)
FAN1_LED_R1: length 3.5
  TOP w0.254: R28.2 68.36,48.6 v3(69.22,48.6) LED1.C2
  BOTTOM w0.254: v3(69.22,48.6) v1(70.36,48.6)
FAN1_OUT_PWM: length 8.4
  TOP w0.254: R11.1 v3(40.97,45.09)
  BOTTOM w0.254: v1(41.68,45.81) 40.97,45.1 v3(40.97,45.09) 40.64,45.42 40.64,46.99 41.68,48.03 U2.3
FAN1_PRESENT: length 141.7
  TOP w0.127: U7.M7 126.28,18.94 125.49,18.94
  TOP w0.254: U2.16 28.98,47.47 30.23,46.23 30.23,44.96 29.84,44.58 R7.2 30.02,44.27 30.51,43.79 30.51,42.93 29.84,42.27 29.84,40.25 29.17,39.58 26.76,39.58 25.87,38.7 v3(25.87,35.05) 25.87,23.21 27.24,21.84 42.55,21.84 47.75,27.05 82.72,27.05 88.08,21.69 113.4,21.69 116.19,18.9 120.68,18.9 121.33,18.25 124.16,18.25 124.86,18.94 125.49,18.94
  BOTTOM w0.254: v1(25.87,36.83) v3(25.87,35.05)
FAN1_PWM: length 83.6
  TOP w0.254: U7.N5 125.81,20.22 123.09,20.22 122.94,20.07 121.67,20.07 121.31,20.42 116.83,20.42 114.03,23.22 88.72,23.22 82.34,29.59 74.17,29.59 67.82,35.94 v3(56.13,35.94) Q4.2
  BOTTOM w0.254: v3(56.13,35.94) v1(56.13,36.96)
FAN1_PWM_P: length 9.8
  TOP w0.254: R11.2 41.02,43.31 v3(41.02,42.55) ; R11.2 41.33,43.36 42.29,44.32 R12.1 43.05,44.32 43.56,43.81 43.56,43.03 44.96,41.64 Q3.D ; R11.2 R10.2
  BOTTOM w0.254: v1(42.04,42.55) v3(41.02,42.55)
FAN1_S_GND: length 3.6
  TOP w0.254: R18.2 v3(47.12,38.73) 45.92,38.73 Q3.S
  BOTTOM w0.381: v3(47.12,38.73) 47.62,38.73 v1(48.26,38.1)
FAN1_SENSOR_IN: length 94.4
  TOP w0.127: U7.M4 126.31,20.57 125.22,20.57
  TOP w0.254: 125.22,20.57 125.17,20.62 124.28,20.62 123.83,21.08 122.56,21.08 121.4,22.24 119.97,22.24 R55.1 119.83,21.92 119.35,21.44 117.25,21.44 114.43,24.26 89.11,24.26 82.76,30.61 74.59,30.61 68.11,37.08 v3(60.58,37.08) 53.47,37.08 50.9,39.65 46.87,39.65 46.1,40.42 46.1,41.58 R14.1
  BOTTOM w0.254: v3(60.58,37.08) v1(60.58,38.1)
FAN1_SENSOR_IN_R: length 7.2
  TOP w0.254: R14.2 v3(44.32,45.09)
  BOTTOM w0.254: U2.2 44.22,46.76 43.81,46.35 v1(43.81,45.85) 43.81,45.59 v3(44.32,45.09)
FAN1_SENSOR_OUT: length 92.3
  TOP w0.254: R17.2 46.61,42.34 46.61,40.63 47.08,40.16 51.11,40.16 53.42,37.85 v3(65.15,37.85) 68.07,37.85 74.8,31.11 82.97,31.11 88.84,25.25 111.86,25.25 112.39,25.78 115.91,25.78 117.9,23.79 119.58,23.79 119.83,23.54 R54.1 120.2,22.75 121.61,22.75 122.77,21.59 123.84,21.59 124.45,20.98 125.84,20.98 U7.N4
  BOTTOM w0.254: v3(65.15,37.85) v1(65.15,38.86)
FAN1_SENSOR_OUT_R: length 9
  TOP w0.254: v3(45.59,45.09) R17.1
  BOTTOM w0.254: v1(44.73,43.74) 45.59,44.6 v3(45.59,45.09) 45.59,46.99 46.76,48.16 U2.1
FAN1F_VCP: length 3.5
  TOP w0.254: U3.4 41.52,29.13 42.18,28.47 v3(42.25,28.47) 42.73,28 C17.2
  BOTTOM w0.254: v3(42.25,28.47) 42.25,28.87 v1(41.78,29.34)
FAN1R_VCP: length 4.2
  TOP w0.254: C10.2 32.69,28.1 v3(32.22,28.57) 32.13,28.57 31.49,29.22 U1.4
  BOTTOM w0.254: v1(31.75,30.1) 31.75,29.04 v3(32.22,28.57)
FAN2_IN_PWM: length 8.1
  TOP w0.254: R33.1 109.03,45.08 109.03,45.47 v3(108.9,45.6)
  BOTTOM w0.254: v1(107.95,45.85) 108.2,45.6 v3(108.9,45.6) 109.08,45.78 109.08,47.01 108.04,48.04 U5.4
FAN2_LED_G: length 28.6
  TOP w0.254: U7.J1 129.08,24.11 128.52,24.67 128.52,28.57 128.4,28.7 128.4,33.32 136.32,41.25 v3(136.32,43.43) R69.1
  BOTTOM w0.254: v3(136.32,43.43) v1(137.41,43.43)
FAN2_LED_G1: length 3.3
  TOP w0.254: LED2.C1 v3(138.18,47.2) 137.28,47.2 R69.2
  BOTTOM w0.254: v1(137.16,47.2) v3(138.18,47.2)
FAN2_LED_R: length 31.5
  TOP w0.127: 128.02,24.77 128.71,24.07 128.71,22.91 U7.J2
  TOP w0.254: R68.1 135.64,48.64 135.25,48.26 v3(135.25,46.35) 135.25,40.9 127.89,33.53 127.89,28.49 128.02,28.36 128.02,24.77
  BOTTOM w0.254: v3(135.25,46.35) v1(134.24,46.35)
FAN2_LED_R1: length 3.3
  TOP w0.254: R68.2 v3(138.18,48.64) 139.5,48.64 LED2.C2
  BOTTOM w0.254: v3(138.18,48.64) v1(139.19,48.64)
FAN2_OUT_PWM: length 8
  TOP w0.254: v3(109.71,45.6) 109.56,45.45 109.56,45.09 R34.1
  BOTTOM w0.254: v1(110.62,45.85) 110.37,45.6 v3(109.71,45.6) 109.58,45.73 109.58,46.97 110.58,47.97 U5.3
FAN2_PRESENT: length 82
  TOP w0.254: U7.M1 126.6,23.34 125.72,24.22 124.94,24.22 124.86,24.15 123.81,24.15 123.29,24.67 120.56,27.41 111.76,27.41 111.12,26.77 91.08,26.77 v3(85.85,32) 83.63,34.23 83.63,38.93 84.29,39.58 98.07,39.58 98.95,40.46 98.95,42.42 99.97,43.44 99.97,44.3 99.49,44.78 R32.2 99.31,45.98 97.88,47.41 U5.16
  BOTTOM w0.254: v3(85.85,32) v1(85.85,30.86)
FAN2_PWM: length 16.8
  TOP w0.254: Q6.2 120.4,34.29 v3(121.73,32.96) 121.73,28.39 123.83,26.29 124.77,26.29 127.48,23.58 U7.L1
  BOTTOM w0.254: v3(121.73,32.96) v1(122.68,32.96)
FAN2_PWM_P: length 12.2
  TOP w0.254: Q5.D 116.35,38.59 115.7,39.24 v3(115.19,39.24) 112.14,42.29 R36.1 111.51,43.18 110.82,43.87 R34.2 R33.2
  BOTTOM w0.254: v3(115.19,39.24) v1(115.19,38.1)
FAN2_S_GND: length 3.3
  TOP w0.381: R60.2 v3(119.55,38.61) 119.36,38.8 Q5.S
  BOTTOM w0.381: v3(119.55,38.61) v1(119.55,37.59)
FAN2_SENSOR_IN: length 31.3
  TOP w0.127: 127.58,23.98 127.91,23.65 127.91,22.91 U7.K2
  TOP w0.254: R38.1 v3(113.22,42.2) 115.67,39.75 120.73,39.75 122.75,37.74 122.75,31.25 R61.1 125.4,29.16 125.6,28.96 125.6,28.02 126.42,27.21 126.42,25.33 127.58,24.16 127.58,23.98
  BOTTOM w0.254: v3(113.22,42.2) v1(113.22,41.21)
FAN2_SENSOR_IN_R: length 7.3
  TOP w0.254: R38.2 v3(113.22,45.09)
  BOTTOM w0.254: U5.2 113.12,46.32 v1(112.65,45.85) 112.65,45.66 v3(113.22,45.09)
FAN2_SENSOR_OUT: length 29.9
  TOP w0.254: R39.2 114.49,41.65 115.8,40.34 120.86,40.34 123.41,37.8 v3(123.41,35.52) 123.41,32.24 R62.1 126.91,29.16 127.17,28.9 127.17,28.49 127.51,28.15 127.51,24.74 128.28,23.96 U7.K1
  BOTTOM w0.254: v3(123.41,35.52) v1(124.32,35.52)
FAN2_SENSOR_OUT_R: length 9
  TOP w0.254: v3(114.49,45.09) R39.1
  BOTTOM w0.254: v1(113.54,43.81) 114.49,44.77 v3(114.49,45.09) 114.49,46.8 115.66,47.97 U5.1
FAN2F_VCP: length 3.5
  TOP w0.254: U6.4 108.83,31.04 109.49,30.38 v3(109.56,30.38) 110.04,29.9 C37.2
  BOTTOM w0.254: v3(109.56,30.38) 109.56,30.78 v1(109.09,31.24)
FAN2R_VCP: length 3.5
  TOP w0.254: U4.4 89.84,34.17 89.18,33.51 v3(89.18,33.44) 88.7,32.97 C26.2
  BOTTOM w0.254: v1(90.04,33.91) 89.58,33.44 v3(89.18,33.44)
FAN3_IN_PWM: length 8
  TOP w0.254: v3(177.8,45.6) 177.93,45.47 177.93,45.08 R107.1
  BOTTOM w0.254: U10.4 176.94,48.1 177.98,47.07 177.98,45.78 v3(177.8,45.6) 177.16,45.6 v1(176.91,45.85)
FAN3_LED_G: length 108
  TOP w0.127: 136.86,14.22 136.72,14.36 136.35,14.36 135.76,14.95 134.32,14.95 133.93,15.34 U7.C11
  TOP w0.254: 136.86,14.22 136.94,14.22 137.47,13.69 138.88,13.69 142.69,9.88 146.53,9.88 149.37,7.04 172.79,7.04 192.68,26.92 v3(202.95,26.92) 211.07,35.05 211.07,41.09 205.49,46.67 205.49,47.04 R116.1
  BOTTOM w0.254: v1(201.8,26.92) v3(202.95,26.92)
FAN3_LED_G1: length 3.8
  TOP w0.254: LED3.C1 v3(207.01,47.2) 206.24,47.2 R116.2
  BOTTOM w0.254: v3(207.01,47.2) 207.69,47.88 v1(208.28,47.88)
FAN3_LED_R: length 106.5
  TOP w0.254: U7.A11 135.79,15.34 136.47,14.66 137.01,14.66 137.46,14.2 139.09,14.2 142.9,10.39 146.74,10.39 149.58,7.54 172.58,7.54 192.85,27.81 202.82,27.81 v3(204.09,29.08) 210.27,35.26 210.27,41.18 204.64,46.81 204.64,47.99 R115.1
  BOTTOM w0.254: v1(205.1,29.08) v3(204.09,29.08)
FAN3_LED_R1: length 3.3
  TOP w0.254: R115.2 206.24,48.6 v3(207.01,48.6) LED3.C2
  BOTTOM w0.254: v3(207.01,48.6) v1(207.01,49.66)
FAN3_OUT_PWM: length 8
  TOP w0.254: v3(178.61,45.6) 178.46,45.45 178.46,45.09 R108.1
  BOTTOM w0.254: U10.3 179.48,48.03 178.48,47.04 178.48,45.73 v3(178.61,45.6) 179.46,45.6 v1(179.58,45.72)
FAN3_PRESENT: length 57.1
  TOP w0.127: 136.09,22.97 135.11,22.97 U7.B2
  TOP w0.254: U10.16 166.78,47.47 168.21,46.04 R103.2 168.39,44.78 168.87,44.3 168.87,43.44 167.89,42.47 167.89,40.51 166.97,39.58 166.44,39.58 165.23,39.58 164.08,38.44 v3(164.08,36.32) 164.59,35.81 164.59,33.74 157.27,26.42 v3(151.64,26.42) ; v3(141.73,26.04) 141.73,25.98 141.48,25.73 140.59,25.73 139.52,24.66 139.01,24.66 138.69,24.34 137.46,24.34 136.09,22.97
  BOTTOM w0.254: v3(141.73,26.04) 143.64,26.04 143.94,26.34 151.18,26.34 151.26,26.42 v3(151.64,26.42) ; v3(164.08,36.32) v1(164.08,37.34)
FAN3_PWM: length 72.1
  TOP w0.254: v3(137.79,23.75) 137.37,23.75 136.23,22.62 135.56,22.62 U7.A2 ; v3(175.03,15.76) 189.1,29.83 v3(189.1,31.75) 189.1,33.91 188.59,34.42 Q8.2
  BOTTOM w0.254: v3(137.79,23.75) 138.26,23.75 139.53,25.02 151.93,25.02 159.26,17.69 159.26,16.51 160.53,15.24 174.51,15.24 v3(175.03,15.76) ; v3(189.1,31.75) v1(189.1,32.66)
FAN3_PWM_P: length 11.6
  TOP w0.254: Q7.D 184.67,38.59 182.75,40.51 R109.1 v3(182.12,41.66) 179.91,43.87 R108.2 R107.2
  BOTTOM w0.254: v1(181.23,42.16) 181.61,42.16 v3(182.12,41.66)
FAN3_S_GND: length 3.5
  TOP w0.381: R114.2 188.85,38.86 v3(187.83,38.86) 186.73,38.86 Q7.S
  BOTTOM w0.381: v3(187.83,38.86) v1(187.83,37.72)
FAN3_SENSOR_IN: length 92.3
  TOP w0.127: U7.B3 135.05,22.11 135.71,22.11
  TOP w0.254: 135.71,22.11 136.23,22.11 137.36,23.24 138.07,23.24 138.67,23.83 138.9,23.83 139.06,24 v3(139.45,24) 141.86,24 141.99,23.88 R74.1 ; v3(176.28,15.57) 190.5,29.79 v3(190.5,35.18) 190.75,35.43 190.75,38.61 189.53,39.84 184.49,39.84 183.97,40.36 183.97,41.52 R111.1
  BOTTOM w0.254: v3(139.45,24) 151.51,24 158.24,17.27 158.24,16.09 160.11,14.22 174.93,14.22 v3(176.28,15.57) ; v3(190.5,35.18) v1(190.5,36.2)
FAN3_SENSOR_IN_R: length 7.2
  TOP w0.254: R111.2 v3(182.12,45.09)
  BOTTOM w0.254: v3(182.12,45.09) 181.61,45.6 v1(181.61,45.85) 181.61,46.07 182.02,46.48 U10.2
FAN3_SENSOR_OUT: length 92.3
  TOP w0.254: U7.A3 135.5,21.75 136.38,21.75 137.51,22.89 138.22,22.89 138.45,23.11 v3(139.32,23.11) 141.48,23.11 141.73,22.86 R75.1 ; R113.2 184.47,42.28 184.47,40.57 184.7,40.34 190.03,40.34 191.39,38.99 v3(191.39,33.91) 191.39,29.75 v3(176.21,14.56)
  BOTTOM w0.254: v1(192.05,34.54) 192.02,34.54 v3(191.39,33.91) ; v3(176.21,14.56) 175.36,13.72 159.9,13.72 153.67,19.94 153.67,21.13 151.3,23.5 139.87,23.5 139.49,23.11 v3(139.32,23.11)
FAN3_SENSOR_OUT_R: length 9
  TOP w0.254: v3(183.39,45.09) R113.1
  BOTTOM w0.254: v1(182.63,43.69) 182.76,43.82 182.76,44.45 v3(183.39,45.09) 183.39,47 184.56,48.16 U10.1
FAN3F_VCP: length 3.5
  TOP w0.254: U11.4 179.7,29.13 180.36,28.47 v3(180.43,28.47) 180.43,28.16 C58.2
  BOTTOM w0.254: v3(180.43,28.47) 180.43,28.87 v1(179.96,29.34)
FAN3R_VCP: length 3.7
  TOP w0.254: U9.4 170.17,28.96 170.56,28.57 v3(170.9,28.57) 171.38,28.1 C51.2
  BOTTOM w0.254: v1(170.43,29.46) 170.43,29.04 v3(170.9,28.57)
FAN4_IN_PWM: length 8.1
  TOP w0.254: R126.1 246.83,45.08 246.83,45.47 v3(246.7,45.6)
  BOTTOM w0.254: U14.4 245.84,48.04 246.88,47 246.88,45.78 v3(246.7,45.6) 245.99,45.6 v1(245.75,45.85)
FAN4_LED_G: length 167.8
  TOP w0.127: 133.45,13.05 133.45,13.05 133.51,13.11 133.51,13.59 133.51,13.59 133.51,13.81 133.45,13.88 133.45,13.89 133.44,13.9 133.44,14.18 U7.D12
  TOP w0.254: 133.45,13.05 133.45,12.98 134.49,11.94 134.49,10.65 136.48,8.66 137.45,8.66 143.64,2.46 174.69,2.46 183.02,10.79 225.43,10.79 238.53,23.9 246.94,23.9 248.95,25.91 252.35,25.91 253.87,27.43 257.18,27.43 272.85,43.11 v3(272.85,44.58) R135.1
  BOTTOM w0.254: v3(272.85,44.58) v1(271.91,44.58)
FAN4_LED_G1: length 5
  TOP w0.254: LED4.C1 v3(274.7,47.2) 274.1,47.2 R135.2
  BOTTOM w0.254: v3(274.7,47.2) 274.7,46.86 v1(274.07,46.23)
FAN4_LED_R: length 167.5
  TOP w0.254: R134.1 271.78,48.51 271.4,48.13 v3(271.4,46.99) 271.4,42.55 256.92,28.07 253.79,28.07 252.14,26.42 248.73,26.42 246.73,24.41 238.28,24.41 225.17,11.3 182.81,11.3 174.48,2.97 143.85,2.97 137.66,9.17 136.69,9.17 134.85,11.01 134.85,12.18 133.88,13.15 U7.C13
  BOTTOM w0.254: v1(271.4,47.9) v3(271.4,46.99)
FAN4_LED_R1: length 4.7
  TOP w0.254: LED4.C2 v3(274.7,48.6) 273.84,48.6 R134.2
  BOTTOM w0.254: v1(273.94,49.4) 274.7,48.64 v3(274.7,48.6)
FAN4_OUT_PWM: length 8
  TOP w0.254: R127.1 247.36,45.09 247.36,45.45 v3(247.51,45.6)
  BOTTOM w0.254: v1(248.41,45.85) 248.16,45.6 v3(247.51,45.6) 247.4,45.72 247.4,46.99 248.38,47.97 U14.3
FAN4_PRESENT: length 131.6
  TOP w0.254: U7.A12 135.76,14.54 137.01,13.29 137.92,13.29 138.11,13.1 138.75,13.1 142.48,9.37 146.31,9.37 149.16,6.53 173,6.53 187.17,20.7 188.64,20.7 193.44,25.5 203.57,25.5 216.11,38.04 v3(217.49,38.04) 218.82,39.37 235.7,39.37 236.54,40.21 236.54,42.01 237.77,43.24 237.77,44.3 237.29,44.78 R125.2 237.11,45.97 235.68,47.4 U14.16
  BOTTOM w0.254: v3(217.49,38.04) v1(217.49,38.95)
FAN4_PWM: length 142.7
  TOP w0.127: 135.11,13.43 135.11,13.83 134.84,14.11 134.59,14.11 134.31,14.39 134.31,14.63 134.04,14.91 133.51,14.91 U7.D11
  TOP w0.254: Q10.2 254.63,34.42 254.89,34.16 254.89,32.04 v3(253.09,30.24) 251.3,28.45 247.86,28.45 245.86,26.44 237.19,26.44 224.34,13.59 182.22,13.59 173.63,5 148.53,5 145.68,7.85 141.85,7.85 138.55,11.15 136.81,11.15 136.29,11.66 136.29,12.25 135.11,13.43
  BOTTOM w0.254: v1(251.84,30.23) 251.86,30.24 v3(253.09,30.24)
FAN4_PWM_P: length 10.3
  TOP w0.254: Q9.D v3(251.35,40.13) 250.44,41.04 R130.1 250.44,42.42 248.99,43.87 R127.2 R126.2
  BOTTOM w0.254: v1(251.35,41.05) v3(251.35,40.13)
FAN4_S_GND: length 4.2
  TOP w0.381: v3(256.03,38.73) R133.2 254.83,38.92 Q9.S
  BOTTOM w0.381: v1(254.76,38.23) 255.27,38.73 v3(256.03,38.73)
FAN4_SENSOR_IN: length 155.2
  TOP w0.254: 146,5.85 147.86,3.99 174.05,3.99 182.64,12.57 224.76,12.57 237.61,25.43 246.28,25.43 248.28,27.43 251.72,27.43 257.18,32.89 v3(257.18,36.07) 257.18,39.12 256.54,39.75 253.41,39.75 251.79,41.37 251.79,42.6 R131.1 ; 146,5.85 R88.1 ; 146,5.85 146,6.1 145.26,6.83 141.43,6.83 138,10.26 137.03,10.26 135.89,11.4 135.89,12.15 134.76,13.28 134.76,13.67 U7.B13
  BOTTOM w0.254: v3(257.18,36.07) 257.18,36.83 v1(256.96,37.05)
FAN4_SENSOR_IN_R: length 7.4
  TOP w0.254: R131.2 v3(251.02,45.09)
  BOTTOM w0.254: U14.2 250.92,46.83 250.32,46.23 v1(250.32,45.85) 250.32,45.72 250.95,45.09 v3(251.02,45.09)
FAN4_SENSOR_OUT: length 157.9
  TOP w0.127: 134.4,13.3 134.4,13.5 134.31,13.59 134.31,13.83 133.88,14.26 U7.C12
  TOP w0.254: R132.2 252.29,41.58 253.62,40.26 256.75,40.26 257.94,39.07 v3(257.94,37.97) 257.94,32.93 251.93,26.92 248.52,26.92 246.52,24.92 238.02,24.92 225.04,11.94 182.72,11.94 174.26,3.48 144.06,3.48 142.55,5 R80.1 141.7,5.84 137.87,9.67 136.9,9.67 135.36,11.22 135.36,12.18 134.4,13.13 134.4,13.3
  BOTTOM w0.254: v3(257.94,37.97) 258.83,37.97 v1(258.85,38)
FAN4_SENSOR_OUT_R: length 9
  TOP w0.254: v3(252.29,45.09) R132.1
  BOTTOM w0.254: U14.1 253.46,48.23 252.29,47.06 v3(252.29,45.09) 251.74,44.54 251.74,44.35 v1(251.21,43.81)
FAN4F_VCP: length 3.6
  TOP w0.254: U15.4 245.86,31.93 246.53,31.27 v3(246.59,31.27) 246.59,31.21 C93.2
  BOTTOM w0.254: v3(246.59,31.27) 246.59,31.66 v1(246.13,32.13)
FAN4R_VCP: length 3.7
  TOP w0.254: C82.2 225.84,32.59 v3(226.31,33.06) 226.31,33.4 226.7,33.79 U13.4
  BOTTOM w0.254: v1(227.2,33.53) 226.78,33.53 v3(226.31,33.06)
FAN5_IN_PWM: length 10.3
  TOP w0.254: v3(315.47,43.68) 315.69,43.45 315.69,43.09 R139.1
  BOTTOM w0.254: U17.4 314.75,47.96 315.77,46.94 315.77,43.98 v3(315.47,43.68) 314.96,44.18 v1(314.96,44.83)
FAN5_LED_G: length 247.9
  TOP w0.254: R148.1 341.63,46.43 341.63,42.21 338.94,39.52 336.05,39.52 335.8,39.27 335.8,36.07 337.31,34.55 337.31,17.08 v3(335.95,15.72) ; U7.C1 133.88,23.39 134.93,24.44 135.89,24.44 136.34,24.89 v3(136.35,24.89)
  BOTTOM w0.254: v3(335.95,15.72) 335.45,15.21 297.79,15.21 295.73,17.27 243.97,17.27 241.45,14.76 178.02,14.76 176.36,16.42 168.54,16.42 164.71,20.24 163.19,20.24 161.95,21.49 157.5,21.49 151.91,27.08 150.39,27.08 150.16,26.85 v1(143,26.85) 142.92,26.93 139.4,26.93 138.5,26.04 137.73,26.04 136.58,24.89 v3(136.35,24.89)
FAN5_LED_G1: length 4.1
  TOP w0.254: R148.2 v3(344.68,47.12) 344.8,47 LED5.C1
  BOTTOM w0.254: v3(344.68,47.12) 344.55,46.99 v1(343.66,46.99)
FAN5_LED_R: length 250
  TOP w0.254: R147.1 341.67,47.86 341.67,47.28 341.12,46.74 341.12,42.44 338.71,40.03 335.84,40.03 335.29,39.48 335.29,35.43 336.8,33.92 336.8,17.65 335.29,16.13 335.29,14.64 v3(335.2,14.55) ; U7.A5 136.01,20.14 136.61,19.55 137.37,19.55 137.67,19.84 v3(137.67,20.24)
  BOTTOM w0.254: v3(137.67,20.24) 137.92,20.5 139.04,20.5 139.25,20.29 140.19,20.29 140.7,20.8 146.38,20.8 149.4,17.78 152.02,17.78 v1(152.65,18.41) 153.67,18.41 159.38,12.7 167,12.7 170.31,9.4 173.91,9.4 178.76,14.25 241.66,14.25 244.18,16.76 295.52,16.76 297.62,14.67 335.09,14.67 v3(335.2,14.55)
FAN5_LED_R1: length 4.1
  TOP w0.254: R147.2 v3(344.68,48.51) 344.79,48.4 LED5.C2
  BOTTOM w0.254: v3(344.68,48.51) v1(344.68,49.53)
FAN5_OUT_PWM: length 10.3
  TOP w0.254: R140.1 316.26,43.09 316.26,43.45 v3(316.48,43.68)
  BOTTOM w0.254: U17.3 317.29,48.05 316.28,47.04 316.28,43.88 v3(316.48,43.68) 317.04,44.23 v1(317.04,44.83)
FAN5_PRESENT: length 231.3
  TOP w0.254: U17.16 304.59,48.09 305.94,46.74 305.94,44.4 R136.2 305.16,44.02 304.9,43.76 304.9,40.26 304.65,40.01 298.66,40.01 298.39,39.73 298.39,9.87 v3(298.58,9.68) ; v3(132.55,7.72) 131.73,7.72 130.13,9.32 130.13,11.24 130.68,11.8 U7.G13
  BOTTOM w0.254: v3(298.58,9.68) 296.14,9.68 293.62,12.19 246.08,12.19 243.56,9.68 180.65,9.68 175.8,4.83 149.73,4.83 v1(149.1,4.19) 147.41,2.5 135.33,2.5 132.55,5.29 v3(132.55,7.72)
FAN5_PWM: length 232.3
  TOP w0.254: v3(124.89,21.89) 125.04,21.74 U7.N3 ; Q12.2 324.99,30.73 325.5,30.23 v3(325.5,16.26)
  BOTTOM w0.254: v3(124.89,21.89) 124.89,22.05 123.81,23.13 v1(123.81,26.99) 124.96,28.14 127.12,28.14 127.55,27.71 134.94,27.71 135.32,28.09 152.33,28.09 157.92,22.5 162.37,22.5 163.61,21.26 165.14,21.26 168.96,17.44 176.78,17.44 178.44,15.77 241.03,15.77 243.55,18.29 296.15,18.29 298.21,16.23 325.48,16.23 v3(325.5,16.26)
FAN5_PWM_P: length 12.3
  TOP w0.254: Q11.D 320.93,36.83 v3(320.42,37.34) R143.1 317.25,41.2 R140.2 R139.2
  BOTTOM w0.254: v1(321.44,37.34) v3(320.42,37.34)
FAN5_S_GND: length 3.1
  TOP w0.254: R146.2 323.74,33.42 v3(322.91,33.42) Q11.S
  BOTTOM w0.254: v3(322.91,33.42) 322.71,33.21 v1(322.71,32.38)
FAN5_SENSOR_IN: length 233.1
  TOP w0.254: v3(137.21,17.14) 137.2,17.16 136.16,17.16 135.58,17.74 U7.A8 ; v3(326.26,12.52) 326.52,12.78 326.52,35.35 320.55,41.32 R144.1
  BOTTOM w0.254: v3(326.26,12.52) 325.91,12.88 297.25,12.88 294.89,15.24 244.81,15.24 242.3,12.72 179.39,12.72 174.54,7.87 150.2,7.87 149.3,8.77 149.3,11.82 147.56,13.56 145.94,13.56 145.61,13.89 143.59,13.89 142.75,14.73 v1(142.75,15.24) 142.11,15.24 140.59,16.76 137.59,16.76 v3(137.21,17.14)
FAN5_SENSOR_IN_R: length 9
  TOP w0.254: R144.2 320.55,44.83 v3(320.17,45.21)
  BOTTOM w0.254: v3(320.17,45.21) 319.66,45.72 v1(319.4,45.72) 319.4,47.62 319.83,48.05 U17.2
FAN5_SENSOR_OUT: length 233.9
  TOP w0.254: U7.A9 135.62,16.8 136.41,16.8 v3(136.58,16.64) ; v3(327.02,12.01) 327.02,35.56 321.56,41.02 R145.2
  BOTTOM w0.254: v3(327.02,12.01) 326.87,11.86 325.99,11.86 325.48,12.37 297.04,12.37 294.68,14.73 245.02,14.73 242.51,12.22 179.6,12.22 174.75,7.37 149.99,7.37 148.72,8.64 148.72,11.55 147.22,13.05 145.73,13.05 145.4,13.39 143.05,13.39 v1(143,13.34) 143,13.63 140.49,16.14 137.29,16.14 136.79,16.64 v3(136.58,16.64)
FAN5_SENSOR_OUT_R: length 10.1
  TOP w0.254: v3(321.31,45.09) 321.56,44.83 R145.1
  BOTTOM w0.254: U17.1 322.37,48.05 321.31,46.99 v3(321.31,45.09) 320.8,44.58 v1(320.8,43.94)
FAN5F_VCP: length 4.7
  TOP w0.254: U18.4 314.06,26.3 v3(314.58,25.78) C110.2
  BOTTOM w0.254: v1(314.58,24.64) v3(314.58,25.78)
FAN5R_VCP: length 4.4
  TOP w0.254: U16.4 306.06,26.55 306.32,26.29 v3(306.7,26.29) C103.2
  BOTTOM w0.254: v1(306.58,25.27) 306.58,26.16 v3(306.7,26.29)
FAN6_IN_PWM: length 9.1
  TOP w0.254: v3(384.43,44.7) 384.66,44.48 384.66,44.12 R158.1
  BOTTOM w0.254: v1(383.79,45.59) 383.79,45.34 v3(384.43,44.7) 384.67,44.94 384.67,47 383.65,48.02 U21.4
FAN6_LED_G: length 313.5
  TOP w0.254: R169.1 410.72,46.17 410.72,36.87 410.21,36.37 v3(410.21,35.94) ; v2(133.48,16.54) 133.48,16.51 133.85,16.14 U7.C10
  BOTTOM w0.254: v3(410.21,35.94) 410,35.94 408.14,34.08 399.94,34.08 391.26,25.4 386.5,25.4 378.68,17.58 342.06,17.58 v1(337.06,12.57) 336.68,12.19 330.12,12.19 328.77,10.85 325.57,10.85 325.06,11.35 296.62,11.35 294.26,13.72 245.44,13.72 242.93,11.2 180.02,11.2 175.17,6.35 146.25,6.35 144.57,4.66 138.34,4.66 135.95,7.05 135.95,12.55 134.88,13.62 134.88,15.85 134.49,16.24 133.77,16.24 v2(133.48,16.54)
FAN6_LED_G1: length 3.9
  TOP w0.254: LED6.C1 v3(413.38,47) 412.45,47 R169.2
  BOTTOM w0.254: v1(413.89,46.23) 413.38,46.74 v3(413.38,47)
FAN6_LED_R: length 313.9
  TOP w0.254: v3(409.32,36.2) 410.21,37.08 410.21,46.81 R168.1 ; v2(133.49,17.34) U7.C9
  BOTTOM w0.254: v3(409.32,36.2) 409.32,35.98 407.93,34.59 399.73,34.59 391.05,25.91 386.29,25.91 378.47,18.08 341.35,18.08 335.97,12.7 329.91,12.7 328.56,11.35 325.78,11.35 325.27,11.86 296.83,11.86 294.47,14.22 245.23,14.22 242.72,11.71 179.81,11.71 174.96,6.86 146.04,6.86 144.36,5.17 138.55,5.17 136.46,7.26 136.46,14.29 v1(135.89,14.86) 135.26,15.48 135.26,16.01 134.65,16.62 134.11,16.62 133.49,17.25 v2(133.49,17.34)
FAN6_LED_R1: length 4.3
  TOP w0.254: LED6.C2 v3(413.51,48.4) 413.12,48.01 v1(412.32,48.01)
  BOTTOM w0.254: v3(413.51,48.4) 412.71,48.4 v1(412.32,48.01)
FAN6_OUT_PWM: length 9
  TOP w0.254: v3(385.44,44.7) 385.22,44.48 385.22,44.12 R159.1
  BOTTOM w0.254: v1(385.95,45.59) 385.95,45.21 v3(385.44,44.7) 385.43,44.7 385.18,44.96 385.18,47.1 386.19,48.12 U21.3
FAN6_PRESENT: length 302.7
  TOP w0.254: v3(131.89,7.05) 129.18,7.05 126.87,9.35 126.87,9.78 127.25,10.16 127.76,10.16 128.76,11.16 129.04,11.16 129.44,11.56 129.44,13.42 129.77,13.74 U7.H13 ; U21.16 373.49,48.02 374.89,46.62 374.89,44.38 R150.2 374.07,43.38 374.55,42.9 374.55,41.12 373.07,39.65 360.96,39.65 356.17,34.86 356.17,10.86 v3(356.36,10.67)
  BOTTOM w0.254: v3(356.36,10.67) 355.85,11.18 330.54,11.18 328.38,9.02 296.04,9.02 293.37,11.68 246.29,11.68 243.77,9.17 180.86,9.17 176.01,4.32 150.37,4.32 148.04,1.99 135.12,1.99 v1(131.74,5.37) 131.74,6.9 v3(131.89,7.05)
FAN6_PWM: length 299.7
  TOP w0.127: U7.M5 126.28,19.74 125.55,19.74
  TOP w0.254: 125.55,19.74 124.03,19.74 v3(123.98,19.68) ; v3(395.28,33.47) 395.21,33.4 Q14.2
  BOTTOM w0.254: v3(123.98,19.68) 123.98,20.93 v1(123.44,21.46) 123.44,22.06 122.79,22.71 122.79,27.41 124.54,29.16 127.54,29.16 127.97,28.73 134.52,28.73 134.91,29.12 152.75,29.12 158.34,23.52 162.79,23.52 164.03,22.27 165.56,22.27 169.38,18.45 177.2,18.45 178.86,16.79 240.61,16.79 243.26,19.43 296.44,19.43 298.35,17.53 317.85,17.53 320.44,20.12 374.32,20.12 376.68,22.48 379.99,22.48 385.45,27.94 390.21,27.94 395.28,33.01 v3(395.28,33.47)
FAN6_PWM_P: length 11
  TOP w0.254: R158.2 R159.2 386.28,42.98 v1(387.35,41.91) v3(388.62,41.91) 389.13,41.4 389.13,41.13 Q13.D
  BOTTOM w0.254: v1(387.35,41.91) v3(388.62,41.91)
FAN6_S_GND: length 4.2
  TOP w0.254: Q13.S 394.73,36.21 v1(394.84,36.32) v3(395.99,36.32)
  BOTTOM w0.254: v1(394.84,36.32) v3(395.99,36.32)
FAN6_SENSOR_IN: length 314.5
  TOP w0.254: R163.1 389.9,42.71 389.9,41.08 391.88,39.1 396.13,39.1 398.27,36.96 405,36.96 406.4,35.56 v3(406.65,35.56) ; U7.A6 135.52,19.3 135.85,19.3 136.43,18.72 137.85,18.72 138.71,19.58 v3(138.71,19.66)
  BOTTOM w0.254: v3(406.65,35.56) 406.27,35.56 405.81,35.1 399.52,35.1 390.84,26.42 386.08,26.42 378.26,18.59 340.89,18.59 335.69,13.39 297.46,13.39 295.1,15.75 244.6,15.75 242.09,13.23 179.18,13.23 174.33,8.38 155.35,8.38 152.78,10.95 152.78,13.34 v1(153.54,14.1) 152.15,15.49 150.24,15.49 149.61,16.13 149.61,16.14 147.28,18.47 143.21,18.47 142.37,19.3 141.47,19.3 141.24,19.08 140.69,19.08 140.23,18.62 139.12,18.62 138.71,19.02 v3(138.71,19.66)
FAN6_SENSOR_IN_R: length 8.4
  TOP w0.254: v3(388.62,45.09) 389.76,43.94 R163.2
  BOTTOM w0.254: v3(388.62,45.09) 387.99,45.72 v1(387.99,45.85) 387.99,47.75 388.73,48.5 U21.2
